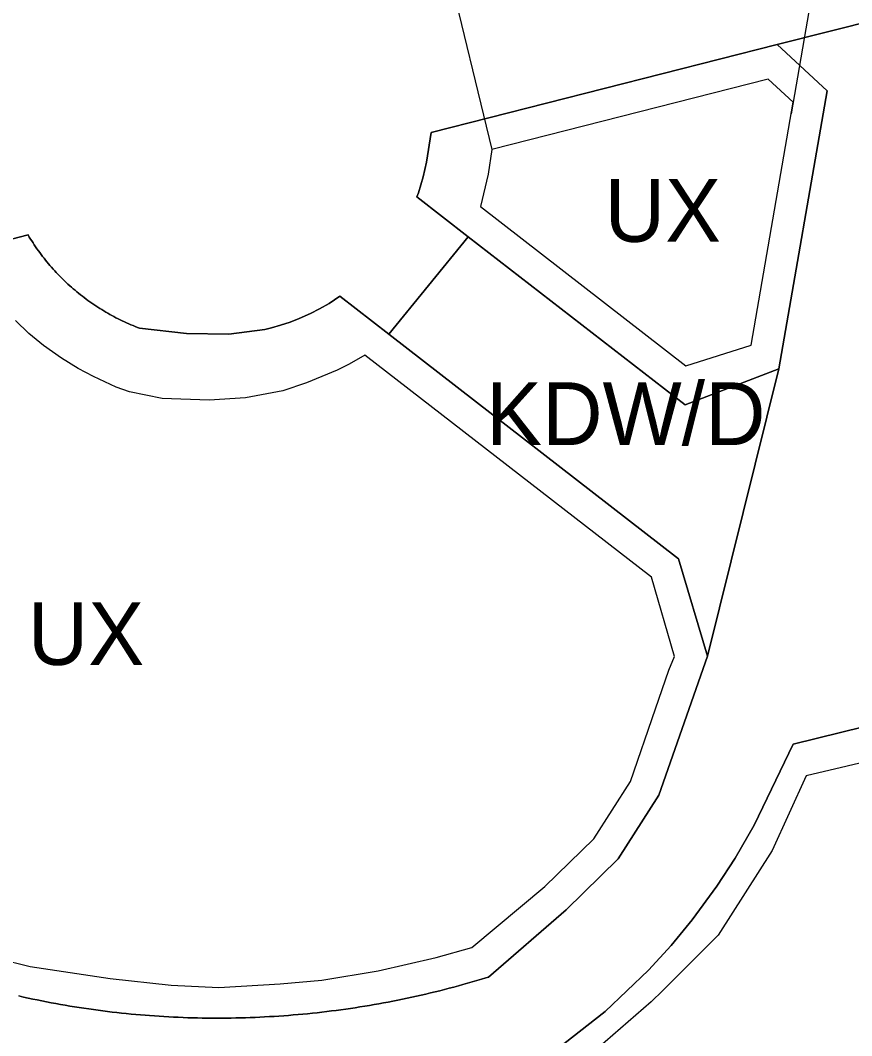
# Model space of a CAD drawing. Extents: x -297746 to -295403, y 27112 to 28877.
# Drawn here: x -297060.2 to -296927.6, y 27583.6 to 27745.5 of the extents above; entities that cross this region are included whole.
import ezdxf

# ---------------------------------------------------------------- set-up
doc = ezdxf.new("R2010")
doc.units = 0
for name, color, linetype in [('linie_rozgraniczajace', 7, 'Continuous'), ('linie_zabudowy_obowiazujace', 7, 'Continuous'), ('oznaczenia_przeznaczen', 7, 'Continuous')]:
    doc.layers.add(name, color=color, linetype=linetype)

msp = doc.modelspace()

# ---------------------------------------------------------------- linework, layer by layer
at = {"layer": 'linie_rozgraniczajace'}
for points in [[(-296434.505, 27869.975), (-296706.45, 27800.862), (-296746.32, 27790.729), (-296906.963, 27749.902), (-296939.511, 27741.63), (-296994.696, 27727.605), (-296995.426, 27722.859), (-296995.977, 27720.526), (-296996.722, 27717.999), (-296996.986, 27717.325), (-296988.793, 27710.975), (-297001.433, 27695.468), (-297009.248, 27701.525), (-297010.984, 27700.354), (-297012.53, 27699.459), (-297013.954, 27698.747), (-297015.744, 27697.933), (-297017.209, 27697.364), (-297018.714, 27696.855), (-297020.158, 27696.448), (-297021.212, 27696.201), (-297026.982, 27695.447)], [(-296994.061, 27590.566), (-296993.319, 27590.75), (-296992.577, 27590.938), (-296991.837, 27591.129), (-296991.097, 27591.325), (-296990.359, 27591.524), (-296989.621, 27591.727), (-296988.885, 27591.934), (-296988.149, 27592.145), (-296987.415, 27592.36), (-296986.682, 27592.578), (-296985.95, 27592.801), (-296985.546, 27592.925), (-296973.157, 27603.67), (-296964.836, 27611.798), (-296958.392, 27621.915), (-296950.616, 27644.079), (-296939.214, 27689.92), (-296931.528, 27734.24), (-296939.511, 27741.63), (-296906.963, 27749.902)], [(-297026.982, 27695.447), (-297033.73, 27695.57), (-297041.25, 27696.407), (-297041.557, 27696.525), (-297041.906, 27696.663), (-297042.254, 27696.804), (-297042.6, 27696.95), (-297042.944, 27697.098), (-297043.287, 27697.251), (-297043.628, 27697.407), (-297043.968, 27697.567), (-297044.305, 27697.73), (-297044.641, 27697.897), (-297044.976, 27698.068), (-297045.308, 27698.242), (-297045.638, 27698.42), (-297045.967, 27698.601), (-297046.294, 27698.785), (-297046.618, 27698.974), (-297046.941, 27699.165), (-297047.261, 27699.36), (-297047.58, 27699.559), (-297047.896, 27699.76), (-297048.21, 27699.966), (-297048.522, 27700.174), (-297048.832, 27700.386), (-297049.139, 27700.601), (-297049.444, 27700.819), (-297049.747, 27701.041), (-297050.048, 27701.266), (-297050.346, 27701.494), (-297050.641, 27701.725), (-297050.934, 27701.959), (-297051.225, 27702.197), (-297051.513, 27702.437), (-297051.798, 27702.681), (-297052.081, 27702.927), (-297052.361, 27703.177), (-297052.639, 27703.429), (-297052.913, 27703.685), (-297053.185, 27703.943), (-297053.455, 27704.205), (-297053.721, 27704.469), (-297053.985, 27704.736), (-297054.245, 27705.006), (-297054.503, 27705.278), (-297054.758, 27705.553), (-297055.01, 27705.831), (-297055.259, 27706.112), (-297055.505, 27706.395), (-297055.748, 27706.681), (-297055.988, 27706.97), (-297056.225, 27707.261), (-297056.459, 27707.554), (-297056.689, 27707.85), (-297056.917, 27708.149), (-297057.141, 27708.45), (-297057.362, 27708.753), (-297057.58, 27709.058), (-297057.794, 27709.366), (-297058.005, 27709.676), (-297058.213, 27709.989), (-297058.418, 27710.303), (-297058.619, 27710.62), (-297058.817, 27710.939), (-297059.011, 27711.26), (-297068.251, 27708.911)], [(-297068.251, 27708.911), (-297059.011, 27711.26), (-297058.817, 27710.939), (-297058.619, 27710.62), (-297058.418, 27710.303), (-297058.213, 27709.989), (-297058.005, 27709.676), (-297057.794, 27709.366), (-297057.58, 27709.058), (-297057.362, 27708.753), (-297057.141, 27708.45), (-297056.917, 27708.149), (-297056.689, 27707.85), (-297056.459, 27707.554), (-297056.225, 27707.261), (-297055.988, 27706.97), (-297055.748, 27706.681), (-297055.505, 27706.395), (-297055.259, 27706.112), (-297055.01, 27705.831), (-297054.758, 27705.553), (-297054.503, 27705.278), (-297054.245, 27705.006), (-297053.985, 27704.736), (-297053.721, 27704.469), (-297053.455, 27704.205), (-297053.185, 27703.943), (-297052.913, 27703.685), (-297052.639, 27703.429), (-297052.361, 27703.177), (-297052.081, 27702.927), (-297051.798, 27702.681), (-297051.513, 27702.437), (-297051.225, 27702.197), (-297050.934, 27701.959), (-297050.641, 27701.725), (-297050.346, 27701.494), (-297050.048, 27701.266), (-297049.747, 27701.041), (-297049.444, 27700.819), (-297049.139, 27700.601), (-297048.832, 27700.386), (-297048.522, 27700.174), (-297048.21, 27699.966), (-297047.896, 27699.76), (-297047.58, 27699.559), (-297047.261, 27699.36), (-297046.941, 27699.165), (-297046.618, 27698.974), (-297046.294, 27698.785), (-297045.967, 27698.601), (-297045.638, 27698.42), (-297045.308, 27698.242), (-297044.976, 27698.068), (-297044.641, 27697.897), (-297044.305, 27697.73), (-297043.968, 27697.567), (-297043.628, 27697.407), (-297043.287, 27697.251), (-297042.944, 27697.098), (-297042.6, 27696.95), (-297042.254, 27696.804), (-297041.906, 27696.663), (-297041.557, 27696.525), (-297041.25, 27696.407), (-297033.73, 27695.57), (-297026.982, 27695.447), (-297021.212, 27696.201), (-297020.158, 27696.448), (-297018.714, 27696.855), (-297017.209, 27697.364), (-297015.744, 27697.933), (-297013.954, 27698.747), (-297012.53, 27699.459), (-297010.984, 27700.354)], [(-297010.984, 27700.354), (-297009.248, 27701.525), (-297001.433, 27695.468), (-296955.209, 27659.641), (-296950.616, 27644.079), (-296958.392, 27621.915), (-296964.836, 27611.798), (-296973.157, 27603.67), (-296985.546, 27592.925), (-296985.95, 27592.801), (-296986.682, 27592.578), (-296987.415, 27592.36), (-296988.149, 27592.145), (-296988.885, 27591.934), (-296989.621, 27591.727), (-296990.359, 27591.524), (-296991.097, 27591.325), (-296991.837, 27591.129), (-296992.577, 27590.938), (-296993.319, 27590.75), (-296994.061, 27590.566), (-296994.805, 27590.386), (-296995.549, 27590.21), (-296996.295, 27590.038), (-296997.041, 27589.87), (-296997.788, 27589.705), (-296998.536, 27589.545), (-296999.285, 27589.388), (-297000.035, 27589.236), (-297000.785, 27589.087), (-297001.536, 27588.942), (-297002.288, 27588.801), (-297003.041, 27588.665), (-297003.794, 27588.532), (-297004.548, 27588.403), (-297005.303, 27588.278), (-297006.058, 27588.156), (-297006.814, 27588.039), (-297007.571, 27587.926), (-297008.328, 27587.817), (-297009.086, 27587.711), (-297009.844, 27587.61), (-297010.603, 27587.513), (-297011.362, 27587.419), (-297012.122, 27587.33), (-297012.882, 27587.244), (-297013.642, 27587.163), (-297014.403, 27587.085), (-297015.165, 27587.012), (-297015.927, 27586.942), (-297016.689, 27586.877), (-297017.451, 27586.815), (-297018.214, 27586.758), (-297018.977, 27586.704), (-297019.741, 27586.654), (-297020.504, 27586.609), (-297021.268, 27586.567), (-297022.032, 27586.53), (-297022.797, 27586.496), (-297023.561, 27586.466), (-297024.326, 27586.441), (-297025.09, 27586.419), (-297025.855, 27586.401), (-297026.62, 27586.388), (-297027.385, 27586.378), (-297028.15, 27586.373), (-297028.915, 27586.371)], [(-296689.133, 27453.416), (-296721.993, 27478.885), (-296770.075, 27516.152), (-296785.976, 27528.476), (-296921.836, 27633.775), (-296936.933, 27630.084), (-296943.148, 27617.146), (-296946.215, 27611.86), (-296949.135, 27607.394), (-296953.049, 27602.075), (-296956.43, 27597.979), (-296960.032, 27594.03), (-296966.95, 27587.428), (-296982.075, 27575.569), (-297001.954, 27560.346), (-297049.986, 27523.564), (-297052.341, 27520.813), (-297060.445, 27511.192), (-297068.206, 27501.892), (-297073.909, 27495.072), (-297080.658, 27487.647), (-297088.887, 27477.865), (-297098.677, 27464.98)], [(-297098.677, 27464.98), (-297088.887, 27477.865), (-297080.658, 27487.647), (-297073.909, 27495.072), (-297068.206, 27501.892), (-297060.445, 27511.192), (-297052.341, 27520.813), (-297049.986, 27523.564), (-297001.954, 27560.346), (-296982.075, 27575.569), (-296966.95, 27587.428), (-296960.032, 27594.03), (-296956.43, 27597.979), (-296953.049, 27602.075), (-296949.135, 27607.394), (-296946.215, 27611.86), (-296943.148, 27617.146), (-296936.933, 27630.084), (-296921.836, 27633.775), (-296785.976, 27528.476), (-296770.075, 27516.152), (-296721.993, 27478.885), (-296853.18, 27327.985)], [(-297060.484, 27589.907), (-297059.746, 27589.741), (-297059.007, 27589.58), (-297058.267, 27589.422), (-297057.527, 27589.268), (-297056.786, 27589.119), (-297056.043, 27588.973), (-297055.301, 27588.831), (-297054.557, 27588.693), (-297053.813, 27588.559), (-297053.068, 27588.429), (-297052.322, 27588.303), (-297051.576, 27588.18), (-297050.829, 27588.062), (-297050.081, 27587.948), (-297049.333, 27587.837), (-297048.584, 27587.731), (-297047.835, 27587.629), (-297047.085, 27587.53), (-297046.334, 27587.436), (-297045.584, 27587.345), (-297044.832, 27587.258), (-297044.08, 27587.176), (-297043.328, 27587.097), (-297042.576, 27587.023), (-297041.823, 27586.952), (-297041.069, 27586.885), (-297040.316, 27586.823), (-297039.615, 27586.768), (-297038.852, 27586.714), (-297038.088, 27586.663), (-297037.325, 27586.617), (-297036.561, 27586.575), (-297035.797, 27586.536), (-297035.033, 27586.502), (-297034.268, 27586.471), (-297033.504, 27586.445), (-297032.739, 27586.423), (-297031.974, 27586.404), (-297031.21, 27586.39), (-297030.445, 27586.38), (-297029.68, 27586.373), (-297028.915, 27586.371), (-297028.15, 27586.373), (-297027.385, 27586.378), (-297026.62, 27586.388), (-297025.855, 27586.401), (-297025.09, 27586.419), (-297024.326, 27586.441), (-297023.561, 27586.466), (-297022.797, 27586.496), (-297022.032, 27586.53), (-297021.268, 27586.567), (-297020.504, 27586.609), (-297019.741, 27586.654), (-297018.977, 27586.704), (-297018.214, 27586.758), (-297017.451, 27586.815), (-297016.689, 27586.877), (-297015.927, 27586.942), (-297015.165, 27587.012), (-297014.403, 27587.085), (-297013.642, 27587.163), (-297012.882, 27587.244), (-297012.122, 27587.33), (-297011.362, 27587.419), (-297010.603, 27587.513), (-297009.844, 27587.61), (-297009.086, 27587.711), (-297008.328, 27587.817), (-297007.571, 27587.926), (-297006.814, 27588.039), (-297006.058, 27588.156), (-297005.303, 27588.278), (-297004.548, 27588.403), (-297003.794, 27588.532), (-297003.041, 27588.665), (-297002.288, 27588.801), (-297001.536, 27588.942), (-297000.785, 27589.087), (-297000.035, 27589.236), (-296999.285, 27589.388), (-296998.536, 27589.545), (-296997.788, 27589.705), (-296997.041, 27589.87), (-296996.295, 27590.038), (-296995.549, 27590.21), (-296994.805, 27590.386), (-296994.061, 27590.566)], [(-297028.915, 27586.371), (-297029.68, 27586.373), (-297030.445, 27586.38), (-297031.21, 27586.39), (-297031.974, 27586.404), (-297032.739, 27586.423), (-297033.504, 27586.445), (-297034.268, 27586.471), (-297035.033, 27586.502), (-297035.797, 27586.536), (-297036.561, 27586.575), (-297037.325, 27586.617), (-297038.088, 27586.663), (-297038.852, 27586.714), (-297039.615, 27586.768), (-297040.316, 27586.823), (-297041.069, 27586.885), (-297041.823, 27586.952), (-297042.576, 27587.023), (-297043.328, 27587.097), (-297044.08, 27587.176), (-297044.832, 27587.258), (-297045.584, 27587.345), (-297046.334, 27587.436), (-297047.085, 27587.53), (-297047.835, 27587.629), (-297048.584, 27587.731), (-297049.333, 27587.837), (-297050.081, 27587.948), (-297050.829, 27588.062), (-297051.576, 27588.18), (-297052.322, 27588.303), (-297053.068, 27588.429), (-297053.813, 27588.559), (-297054.557, 27588.693), (-297055.301, 27588.831), (-297056.043, 27588.973), (-297056.786, 27589.119), (-297057.527, 27589.268), (-297058.267, 27589.422), (-297059.007, 27589.58), (-297059.746, 27589.741), (-297060.484, 27589.907)]]:
    msp.add_lwpolyline(points, dxfattribs=at)
for points in [[(-296954.186, 27684.152), (-296988.793, 27710.975), (-296996.986, 27717.325), (-296996.722, 27717.999), (-296995.977, 27720.526), (-296995.426, 27722.859), (-296994.696, 27727.605), (-296939.511, 27741.63), (-296931.528, 27734.24), (-296939.214, 27689.92)], [(-296950.616, 27644.079), (-296955.209, 27659.641), (-297001.433, 27695.468), (-296988.793, 27710.975), (-296954.186, 27684.152), (-296939.214, 27689.92)]]:
    msp.add_lwpolyline(points, close=True, dxfattribs=at)
at = {"layer": 'linie_zabudowy_obowiazujace'}
for points in [[(-296937.232, 27730.596), (-296928.952, 27778.345)], [(-296992.087, 27754.064), (-296984.99, 27724.914)], [(-296943.628, 27693.714), (-296936.916, 27732.419), (-296940.911, 27736.117), (-296984.99, 27724.914), (-296985.6, 27720.948), (-296986.821, 27715.777), (-296954.044, 27690.373), (-296943.628, 27693.714)], [(-297018.36, 27686.425), (-297024.336, 27685.268), (-297030.09, 27684.919), (-297037.588, 27685.18), (-297042.82, 27686.227), (-297044.95, 27687.019), (-297048.582, 27688.694), (-297051.018, 27689.972), (-297053.669, 27691.591), (-297056.523, 27693.634), (-297058.856, 27695.574), (-297060.99, 27697.602)], [(-297062.546, 27595.544), (-297059.951, 27594.917), (-297058.658, 27594.604), (-297045.911, 27592.701), (-297036.181, 27591.655), (-297028.543, 27591.236), (-297018.789, 27591.864), (-297012.142, 27592.408), (-297003.13, 27593.911), (-296993.909, 27596.037), (-296988.222, 27597.616), (-296976.542, 27607.353), (-296976.539, 27607.356), (-296968.74, 27614.974), (-296962.916, 27624.117), (-296958.912, 27635.721), (-296956.785, 27641.886), (-296955.878, 27644.058), (-296959.545, 27656.68), (-297005.261, 27692.113), (-297007.781, 27690.653), (-297009.67, 27689.683), (-297014.566, 27687.695), (-297018.36, 27686.425)], [(-296890.92, 27603.492), (-296921.794, 27628.095), (-296934.887, 27625.004), (-296940.281, 27613.119), (-296948.897, 27599.591), (-296957.817, 27590.693), (-296957.727, 27590.784), (-296959.603, 27588.951), (-296979.191, 27571.961), (-296997.864, 27556.514), (-297033.238, 27529.905), (-297046.359, 27519.012), (-297072.903, 27489.098)]]:
    msp.add_lwpolyline(points, dxfattribs=at)

# ---------------------------------------------------------------- texts
at = {"layer": 'oznaczenia_przeznaczen'}
for s, p in [('UX', (-296967.029, 27710.17)), ('KDW/D', (-296985.925, 27677.766)), ('UX', (-297059.052, 27642.696))]:
    msp.add_text(s, height=10, dxfattribs=at).set_placement(p)

doc.saveas('drawing.dxf')
